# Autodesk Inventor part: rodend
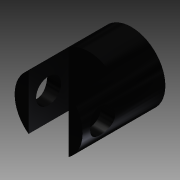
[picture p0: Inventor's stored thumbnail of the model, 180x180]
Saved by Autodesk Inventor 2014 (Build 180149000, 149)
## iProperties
Shininess: 64.0
Length Units: 11272
Angle Units: 11279
Time Units: 11290
Mass Units: 11286
Length Display Precision: 3
Angle Display Precision: 2
Compacted: True
Part Number: rodend
Document SubType Name: Modeling
Created: 2003-01
Designer: dayb
Density: 1 g/cm^3
Mass: 2.04964 g
Surface Area: 19.6743 cm^2
Volume: 2.04964 cm^3
Material: Generic
Appearance: Smooth - Black
Density: 0.0
Volumn: 0.0
Area: 0.0
PropertySet Name: Model Information
Control State: 0
Master: False
Checked Out: False
Author: dayb
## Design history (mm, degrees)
sketch "Sketch1"
  geometry: C1 r 6 at (0, 0) reference; C2 r 8.592 at (0, 0)
  constraints: 1 centre point
extrude "Extrusion1" new body sketch "Sketch1" distance "d0" = 8.255; taper "d1" = 0 deg
sketch "Sketch2"
  geometry: C1 r 8.592 at (0, 0) reference
extrude "Extrusion2" join sketch "Sketch2" distance "d2" = 12.7; taper "d3" = 0 deg
sketch "Sketch3"
  geometry: L1 (-8.592, 12.7)-(8.592, 12.7) reference; L2 (8.592, -8.255)-(-8.592, -8.255) reference; L3 (-5.08, 12.7)-(5.08, 12.7); L4 (5.08, 12.7)-(5.08, 2.54); L5 (5.08, 2.54)-(-5.08, 2.54); L6 (-5.08, 2.54)-(-5.08, 12.7); L7 (0, -12.446)-(0, 16.891) reference
  constraints: 8 end point, 2 parallel, 1 horizontal, 1 perpendicular, 1 point on line
  dimensions: "d4" = 10.16 distance of L3.start L3.end; "d5" = 5.08 distance between parallel lines of L7 L4 (= 0.5 x d4); "d6" = 10.16 distance of L3.end L4.end
extrude "Extrusion3" cut sketch "Sketch3" stored distance "d7" = 3.175; taper "d8" = 0 deg
sketch "Sketch4"
  geometry: L1 (0, 14.351)-(0, 2.794) reference; L2 (-6.93, 12.7)-(6.93, 12.7) reference; C1 r 3.175 at (0, 7.62)
  constraints: 1 centre point, 1 point on line
  dimensions: "d9" = 6.35 diameter of C1; "d10" = 5.08 distance from line of L2 C1.centre
extrude "Extrusion4" cut sketch "Sketch4" stored distance "d11" = 3.175; taper "d12" = 0 deg
body "Solid1"
node "Reference1"
node "Projected Loop1"
